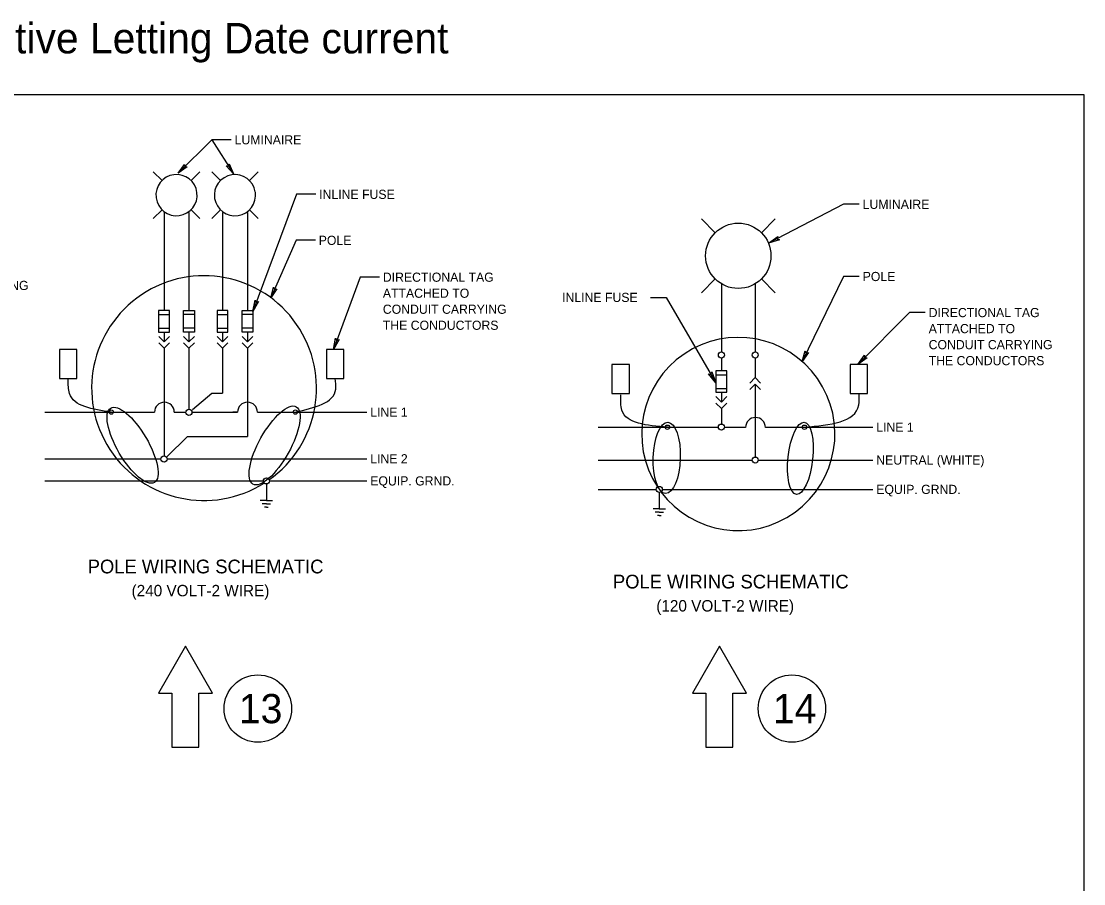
# Model space of a CAD drawing. Extents: x 99981 to 128681, y 99783 to 102182.
# Drawn here: x 122189 to 123581, y 101052 to 102182 of the extents above; entities that cross this region are included whole.
import ezdxf

# ---------------------------------------------------------------- set-up
doc = ezdxf.new("R2010")
doc.units = 0
for name, color, linetype in [('Default', 7, 'Continuous'), ('Level 1', 7, 'Continuous'), ('RD Lighting', 7, 'Continuous'), ('RD Standard Plans Active', 7, 'Continuous')]:
    doc.layers.add(name, color=color, linetype=linetype)

msp = doc.modelspace()

# ---------------------------------------------------------------- linework, layer by layer
at = {"layer": 'Default'}
msp.add_lwpolyline([(120381.4, 102086.3), (123581.1, 102086.3), (123581.1, 99886.7), (120381.4, 99886.7)], close=True, dxfattribs=at)
at = {"layer": 'Level 1'}
for p, q in [((122438.6, 102026.8), (122394.4, 101982.9)), ((122463.9, 102026.8), (122438.6, 102026.8)), ((122438.6, 102026.8), (122466.8, 101982.1)), ((122373.2, 101973.2), (122361.8, 101984.6)), ((122411.3, 101973.2), (122422.7, 101984.6)), ((122449.7, 101973.2), (122438.3, 101984.6)), ((122487.8, 101973.2), (122499.2, 101984.6)), ((122549.4, 101955.3), (122492.3, 101801.8)), ((122574.7, 101955.3), (122549.4, 101955.3)), ((122361.8, 101923.7), (122373.2, 101935.1)), ((122422.7, 101923.7), (122411.3, 101935.1)), ((122438.3, 101923.7), (122449.7, 101935.1)), ((122499.2, 101923.7), (122487.8, 101935.1)), ((123266.3, 101942.2), (123167.9, 101891.1)), ((123286.9, 101942.2), (123266.3, 101942.2)), ((122375.8, 101931.6), (122375.8, 101803.3)), ((122408.5, 101931.6), (122408.5, 101803.3)), ((122452.5, 101931.6), (122452.5, 101803.3)), ((122485.2, 101931.6), (122485.2, 101803.3)), ((123098.1, 101904.9), (123080.1, 101923)), ((123158.6, 101904.9), (123176.7, 101923)), ((122548.8, 101895), (122515.7, 101819.6)), ((122574.1, 101895), (122548.8, 101895)), ((122632.8, 101846.7), (122598, 101752)), ((122658.1, 101846.7), (122632.8, 101846.7)), ((123080.1, 101826.4), (123098.1, 101844.4)), ((123106.2, 101838.1), (123106.2, 101748.7)), ((123150.5, 101838.1), (123150.5, 101748.7)), ((123176.7, 101826.4), (123158.6, 101844.4)), ((123266.3, 101847.6), (123211.9, 101736.3)), ((123286.9, 101847.6), (123266.3, 101847.6)), ((123013.4, 101820.2), (123034, 101820.2)), ((123034, 101820.2), (123099.1, 101708.4)), ((122368.7, 101797.9), (122382.9, 101797.9)), ((122415.6, 101797.9), (122401.4, 101797.9)), ((122445.4, 101797.9), (122459.6, 101797.9)), ((122492.3, 101797.9), (122478.1, 101797.9)), ((123352.8, 101800.3), (123284.8, 101732.1)), ((123373.4, 101800.3), (123352.8, 101800.3)), ((122368.7, 101779.8), (122382.9, 101779.8)), ((122375.8, 101774.8), (122375.8, 101762)), ((122415.6, 101779.8), (122401.4, 101779.8)), ((122408.5, 101774.8), (122408.5, 101762)), ((122445.4, 101779.8), (122459.6, 101779.8)), ((122452.5, 101774.8), (122452.5, 101762)), ((122492.3, 101779.8), (122478.1, 101779.8)), ((122485.2, 101774.8), (122485.2, 101762)), ((122375.8, 101753.5), (122375.8, 101612.3)), ((122408.5, 101753.5), (122408.5, 101674.1)), ((122452.5, 101753.5), (122452.5, 101694.8)), ((122485.2, 101753.5), (122485.2, 101637.9)), ((123106.2, 101740.8), (123106.2, 101724.2)), ((123150.5, 101740.8), (123150.5, 101715)), ((123099.1, 101718.8), (123113.3, 101718.8)), ((123099.1, 101700.8), (123113.3, 101700.8)), ((123150.5, 101706.5), (123150.5, 101610.9)), ((122413.2, 101673.1), (122438.4, 101694.8)), ((122438.4, 101694.8), (122452.5, 101694.8)), ((123106.2, 101695.8), (123106.2, 101683)), ((122219.8, 101669.7), (122363.3, 101669.7)), ((122389.2, 101669.7), (122404.1, 101669.7)), ((122413.2, 101669.7), (122472.2, 101669.7)), ((122472.2, 101669.7), (122465.8, 101669.7)), ((122498.1, 101669.7), (122641.6, 101669.7)), ((123106.2, 101674.5), (123106.2, 101654.2)), ((122944.7, 101650.1), (123102.3, 101650.1)), ((123110.2, 101650.1), (123137.9, 101650.1)), ((123163.8, 101650.1), (123304.7, 101650.1)), ((122379.7, 101611.4), (122406.4, 101637.9)), ((122406.4, 101637.9), (122485.2, 101637.9)), ((122219.8, 101608.7), (122371.9, 101608.7)), ((122380.2, 101608.7), (122641.6, 101608.7)), ((122944.7, 101607), (123146.6, 101607)), ((123154.5, 101607), (123304.7, 101607)), ((122219.8, 101579.7), (122506.1, 101579.7)), ((122510, 101575.7), (122510, 101554)), ((122514, 101579.7), (122641.6, 101579.7)), ((122944.7, 101568.6), (123020.8, 101568.6)), ((123024.7, 101564.6), (123024.7, 101542.9)), ((123028.7, 101568.6), (123304.7, 101568.6)), ((122510, 101554), (122502, 101554)), ((122510, 101549.8), (122504.6, 101549.8)), ((122510, 101545.4), (122507.7, 101545.4)), ((122510, 101554), (122518, 101554)), ((122510, 101549.8), (122515.4, 101549.8)), ((122510, 101545.4), (122512.3, 101545.4)), ((123024.7, 101542.9), (123016.7, 101542.9)), ((123024.7, 101538.7), (123019.3, 101538.7)), ((123024.7, 101534.3), (123022.4, 101534.3)), ((123024.7, 101542.9), (123032.8, 101542.9)), ((123024.7, 101538.7), (123030.2, 101538.7)), ((123024.7, 101534.3), (123027.1, 101534.3))]:
    msp.add_line(p, q, dxfattribs=at)
for points in [[(122406.1, 101991.2), (122394.4, 101982.9), (122402.8, 101994.6), (122402.9, 101991.3)], [(122461.3, 101995.3), (122466.8, 101982.1), (122457.2, 101992.8), (122460.4, 101992.2)], [(123182.3, 101895.7), (123167.9, 101891.1), (123180, 101900.2), (123179.1, 101896.9)], [(122523.6, 101831.5), (122515.7, 101819.6), (122519.2, 101833.5), (122520.5, 101830.5)], [(122499.8, 101814.9), (122492.3, 101801.8), (122495.1, 101816.6), (122496.6, 101813.5)], [(122368.7, 101774.8), (122382.9, 101774.8), (122382.9, 101803.2), (122368.7, 101803.2)], [(122415.6, 101774.8), (122401.4, 101774.8), (122401.4, 101803.2), (122415.6, 101803.2)], [(122445.4, 101774.8), (122459.6, 101774.8), (122459.6, 101803.2), (122445.4, 101803.2)], [(122492.3, 101774.8), (122478.1, 101774.8), (122478.1, 101803.2), (122492.3, 101803.2)], [(122605.5, 101765.1), (122598, 101752), (122600.7, 101766.8), (122602.3, 101763.8)], [(122261.5, 101714.1), (122261.5, 101752), (122238.8, 101752), (122238.8, 101714.1)], [(122611.5, 101714.1), (122611.5, 101752), (122588.8, 101752), (122588.8, 101714.1)], [(123220.2, 101747.9), (123211.9, 101736.3), (123215.9, 101750), (123217.1, 101747)], [(123297.1, 101740.9), (123284.8, 101732.1), (123293.6, 101744.5), (123293.7, 101741)], [(122985.6, 101694.3), (122985.6, 101732.1), (122962.8, 101732.1), (122962.8, 101694.3)], [(123297.7, 101694.3), (123297.7, 101732.1), (123275, 101732.1), (123275, 101694.3)], [(123093.8, 101722.6), (123099.1, 101708.4), (123089.4, 101720.1), (123092.8, 101719.3)], [(123099.1, 101695.8), (123113.3, 101695.8), (123113.3, 101724.1), (123099.1, 101724.1)]]:
    msp.add_lwpolyline(points, close=True, dxfattribs=at)
for points in [[(122368.8, 101769.1), (122375.8, 101762), (122382.9, 101769.1)], [(122415.6, 101769.1), (122408.5, 101762), (122401.4, 101769.1)], [(122445.4, 101769.1), (122452.5, 101762), (122459.6, 101769.1)], [(122492.2, 101769.1), (122485.2, 101762), (122478.1, 101769.1)], [(122368.8, 101760.6), (122375.8, 101753.5), (122382.9, 101760.6)], [(122415.6, 101760.6), (122408.5, 101753.5), (122401.4, 101760.6)], [(122445.4, 101760.6), (122452.5, 101753.5), (122459.6, 101760.6)], [(122492.2, 101760.6), (122485.2, 101753.5), (122478.1, 101760.6)], [(123157.6, 101707.9), (123150.5, 101715), (123143.4, 101707.9)], [(123157.6, 101699.4), (123150.5, 101706.5), (123143.4, 101699.4)], [(123099.1, 101690.1), (123106.2, 101683), (123113.3, 101690.1)], [(123099.1, 101681.6), (123106.2, 101674.5), (123113.3, 101681.6)]]:
    msp.add_lwpolyline(points, dxfattribs=at)
for centre, radius in [((123128.4, 101874.7), 42.8), ((123106.2, 101744.7), 3.97), ((123150.5, 101744.7), 3.97), ((122306.6, 101669.9), 2.84), ((122408.5, 101669.6), 3.97), ((122547.9, 101669.9), 2.84), ((123035.4, 101650.1), 2.84), ((123106.2, 101650.2), 3.97), ((123215.1, 101650.1), 2.84), ((122375.8, 101608.4), 3.97), ((123150.5, 101607), 3.97), ((122510, 101579.7), 3.97), ((123024.8, 101568.6), 3.97)]:
    msp.add_circle(centre, radius, dxfattribs=at)
for centre, radius, start, end in [((122392.2, 101954.2), 27, 187.5804, 186.8813), ((122468.8, 101954.2), 27, 9.404, 8.3629), ((122428.3, 101701.3), 147.3, 305.2734, 302.3954), ((123128.4, 101641.2), 126.6, 216.8263, 213.2275), ((122376.3, 101669.8), 13, 360, 180), ((122485.2, 101669.8), 13, 0, 180), ((123150.9, 101649.8), 13, 0, 180)]:
    msp.add_arc(centre, radius, start, end, dxfattribs=at)
for centre, major_axis, ratio in [((122334.6, 101626.4), (28.6, -48.8), 0.35677), ((122520.7, 101626.1), (-28.3, -50.8), 0.351259), ((123034.6, 101609.9), (-1.5, -46.7), 0.380534), ((123209.7, 101609.3), (-5.1, -47.3), 0.339542)]:
    msp.add_ellipse(centre, major_axis=major_axis, ratio=ratio, dxfattribs=at)
for points in [[(122306.6, 101669.9), (122251.9, 101694.3), (122250.4, 101712.6)], [(122547.9, 101669.9), (122600.9, 101700), (122600, 101713.9)], [(123035.4, 101650.1), (122975.8, 101672.3), (122974.4, 101692.7)], [(123215.1, 101650.1), (123286.3, 101679.3), (123286.7, 101693.2)]]:
    msp.add_spline(points, degree=3, dxfattribs=at)
at = {"layer": 'RD Lighting'}
for points in [[(122403.9, 101363.1), (122368.4, 101301.6), (122386.2, 101301.6), (122386.2, 101230.7), (122421.6, 101230.7), (122421.6, 101301.6), (122439.4, 101301.6)], [(123103.7, 101363.1), (123068.2, 101301.6), (123086, 101301.6), (123086, 101230.7), (123121.4, 101230.7), (123121.4, 101301.6), (123139.2, 101301.6)]]:
    msp.add_lwpolyline(points, close=True, dxfattribs=at)
for centre in [(122498.8, 101281.3), (123198.6, 101281.3)]:
    msp.add_circle(centre, 44.2, dxfattribs=at)

# ---------------------------------------------------------------- texts
at = {"layer": 'Level 1'}
for s, height, p in [(' LUMINAIRE', 12, (122463.9, 102020.8)), (' INLINE FUSE', 12, (122574.7, 101949.3)), (' LUMINAIRE', 12, (123286.9, 101936.2)), (' POLE', 12, (122574.1, 101889)), (' DIRECTIONAL TAG', 12, (122658.1, 101840.7)), (' POLE', 12, (123286.9, 101841.6)), (' CONDUIT CARRYING', 12, (122031.5, 101829.9)), (' ATTACHED TO', 12, (122658.1, 101819.7)), ('INLINE FUSE ', 12, (122897.5, 101814.2)), (' CONDUIT CARRYING', 12, (122658.1, 101798.7)), (' DIRECTIONAL TAG', 12, (123373.4, 101794.3)), (' THE CONDUCTORS', 12, (122658.1, 101777.7)), (' ATTACHED TO', 12, (123373.4, 101773.3)), (' CONDUIT CARRYING', 12, (123373.4, 101752.3)), (' THE CONDUCTORS', 12, (123373.4, 101731.3)), (' LINE 1', 12, (122641.6, 101663.7)), (' LINE 1', 12, (123304.7, 101644.1)), (' LINE 2', 12, (122641.6, 101602.7)), (' NEUTRAL (WHITE)', 12, (123304.7, 101601)), (' EQUIP. GRND.', 12, (122641.6, 101573.7)), (' EQUIP. GRND.', 12, (123304.7, 101562.6)), ('POLE WIRING SCHEMATIC', 18, (122275.8, 101458.5)), ('POLE WIRING SCHEMATIC', 18, (122964.1, 101438.7)), ('(240 VOLT-2 WIRE)', 15, (122333.3, 101428.4)), ('(120 VOLT-2 WIRE)', 15, (123020.9, 101408.5))]:
    msp.add_text(s, height=height, dxfattribs=at).set_placement(p)
at = {"layer": 'RD Lighting'}
for s, p in [('13', (122473.9, 101262.1)), ('14', (123173.7, 101262.1))]:
    msp.add_text(s, height=38.31, dxfattribs=at).set_placement(p)
at = {"layer": 'RD Standard Plans Active'}
msp.add_text('Effective Letting Date current', height=40, dxfattribs=at).set_placement((122058.8, 102140))

doc.saveas('drawing.dxf')
